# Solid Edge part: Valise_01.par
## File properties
Author: Bernard DUMAS
Template: Normal.par
Last saved by: FR026244
Revision: 12
Application: Solid Edge
Material: Bois, Frêne
Style de face: Jaune kaki
Style de remplissage: Liège
Style virtuel: Frêne verni
Coef. of Thermal Exp: 0.0
Thermal Conductivity: 0.0
Specific Heat: 0.0
Modulus of Elasticity: 0.0
Poission's Ratio: 0.0
Yield Stress: 0.0
Ultimate Stress: 0.0
Elongation: 0.0
Densité: 460.000 kg/m^3
Précision: 0.9900
Document Number: 01
Revision: a
Project Name: Slamson
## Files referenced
..\Valise_Salmson.asm
bD:\Documents and Settings\FR026244\Mes Documents\Bernard\Slamson\Valise-Salmson\Valise_Salmson.asm
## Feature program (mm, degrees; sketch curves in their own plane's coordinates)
sketch for "unnamed Protrusion 1" plane through (0, 0, 0) normal (0, -1, 0) x-axis (1, 0, 0)
extrude "unnamed Protrusion 1" add finite 850 symmetric
extrude "unnamed Cutout 1" cut finite 6
extrude "Enlèvement_matière_2" cut finite 6
fillet "Congé_1" radius 3
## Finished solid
Body 1: solid body, 11 faces, 24 edges, 16 vertices.
  Faces by surface: plane 9, cylinder 2
  Edges by curve: line 20, circle 4
Bounding box of the edges (mm): 505.000 x 850.000 x 6.000, from (0, -425, 0) to (505, 425, 6).
Cylindrical faces by radius (mm): R3 x2
Planar faces by outward normal: +y 2, +z 2, -x 1, -y 2, -z 1, oblique 1
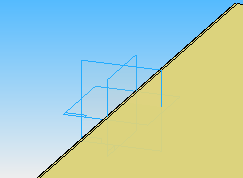
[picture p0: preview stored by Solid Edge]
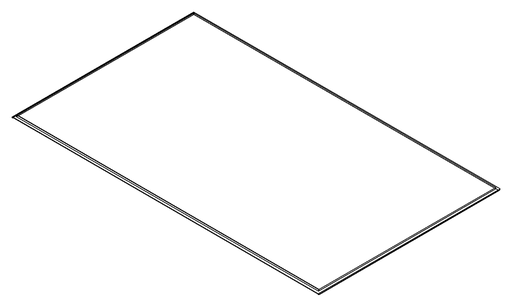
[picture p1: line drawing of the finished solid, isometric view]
